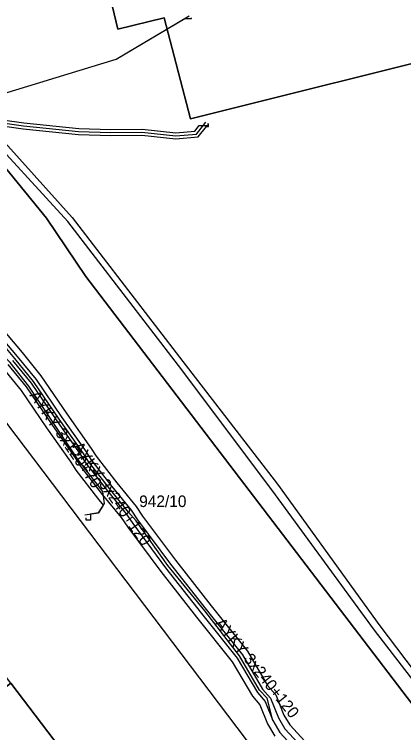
# Model space of a CAD drawing. Extents: x -793400 to -756198, y -1074141 to -1042963.
# Drawn here: x -783067.47 to -783042.2, y -1065160.27 to -1065113.69 of the extents above; entities that cross this region are included whole.
import ezdxf

# ---------------------------------------------------------------- set-up
doc = ezdxf.new("R2010")
doc.units = 0
for name, color, linetype in [('Parcela', 7, 'Continuous'), ('Popiskový text - Parcela', 7, 'Continuous'), ('Popiskový text - Vedení nn kabelové', 7, 'Continuous'), ('Spojnice nn', 7, 'Continuous'), ('Spojnice vn', 7, 'Continuous'), ('Stavební objekt', 7, 'Continuous'), ('Vedení 22 kV kabelové', 7, 'Continuous'), ('Vedení nn kabelové', 7, 'Continuous')]:
    doc.layers.add(name, color=color, linetype=linetype)

msp = doc.modelspace()

# ---------------------------------------------------------------- linework, layer by layer
at = {"layer": 'Parcela'}
msp.add_lwpolyline([(-783145.19, -1065118.78), (-783065.04, -1065096.7), (-783060.76, -1065114.64), (-783057.74, -1065113.92), (-783056.04, -1065120.47), (-783037.14, -1065115.76), (-783036.87, -1065116.85), (-783031.97, -1065115.65), (-783032.24, -1065114.53), (-783028.46, -1065113.59), (-783029.14, -1065110.87), (-783025.94, -1065110.07), (-783026.78, -1065106.68), (-783029.99, -1065107.48), (-783034.78, -1065088.26), (-783031.87, -1065087.44), (-782993.91, -1065091.32), (-782972.88, -1065081.39), (-782969.74, -1065082.74), (-782964.46, -1065085)], dxfattribs=at)
for points in [[(-783034.78, -1065088.26), (-783029.99, -1065107.48), (-783026.78, -1065106.68), (-783025.94, -1065110.07), (-783029.14, -1065110.87), (-783028.46, -1065113.59), (-783032.24, -1065114.53), (-783031.97, -1065115.65), (-783036.87, -1065116.85), (-783037.14, -1065115.76), (-783056.04, -1065120.47), (-783057.74, -1065113.92), (-783060.76, -1065114.64), (-783065.04, -1065096.7), (-783065.15, -1065096.23), (-783059.74, -1065094.99), (-783061.01, -1065091.04), (-783054.08, -1065089.37), (-783054.18, -1065088.96), (-783035.72, -1065084.5)], [(-783062.82, -1065130.68), (-783065.38, -1065126.9), (-783070.16, -1065121.07), (-783078.17, -1065126.78), (-783086.05, -1065132.94), (-783082.37, -1065137.77), (-783083.31, -1065138.48), (-783079.56, -1065143.43), (-783078.61, -1065142.71), (-783071.47, -1065152.1), (-783072.41, -1065152.82), (-783068.64, -1065157.77), (-783067.7, -1065157.05), (-783060.55, -1065166.44), (-783061.49, -1065167.16), (-783057.74, -1065172.09), (-783056.8, -1065171.37), (-783053.14, -1065176.18), (-783045.29, -1065170.16), (-783037.3, -1065164.1)], [(-783062.82, -1065130.68), (-783037.3, -1065164.1), (-783045.29, -1065170.16), (-783053.14, -1065176.18), (-783056.8, -1065171.37), (-783057.74, -1065172.09), (-783061.49, -1065167.16), (-783060.55, -1065166.44), (-783067.7, -1065157.05), (-783068.64, -1065157.77), (-783072.41, -1065152.82), (-783071.47, -1065152.1), (-783078.61, -1065142.71), (-783079.56, -1065143.43), (-783083.31, -1065138.48), (-783082.37, -1065137.77), (-783086.05, -1065132.94), (-783078.17, -1065126.78), (-783070.16, -1065121.07), (-783065.38, -1065126.9)]]:
    msp.add_lwpolyline(points, close=True, dxfattribs=at)
at = {"layer": 'Spojnice nn'}
for points in [[(-783078.01, -1065124.77), (-783077.24, -1065124.21), (-783075.95, -1065123.29), (-783072.89, -1065121.04), (-783069.49, -1065120.55), (-783066.87, -1065120.92), (-783063.3, -1065121.29), (-783061.2, -1065121.35), (-783059.19, -1065121.33), (-783056.99, -1065121.57), (-783055.65, -1065121.45), (-783055.03, -1065120.68)], [(-783050.69, -1065159.48), (-783051.06, -1065158.04), (-783051.55, -1065157.52), (-783052.86, -1065155.29), (-783055.11, -1065152.36), (-783057.5, -1065149.43), (-783059.56, -1065146.54), (-783060.05, -1065145.96), (-783061.29, -1065144.44), (-783062.66, -1065142.68), (-783062.98, -1065142.17), (-783064.55, -1065139.94), (-783066.22, -1065137.49), (-783067.43, -1065136.01), (-783068.97, -1065134.2), (-783070.39, -1065132.31), (-783070.82, -1065131.77), (-783072.05, -1065130.11), (-783073.91, -1065127.65), (-783075.94, -1065124.77), (-783078.01, -1065124.77)], [(-783062.9, -1065146.15), (-783062, -1065146.02), (-783061.62, -1065145.4), (-783061.73, -1065144.64), (-783063.32, -1065142.58), (-783064.91, -1065140.21), (-783066.52, -1065137.8), (-783067.74, -1065136.26), (-783069.38, -1065134.66), (-783071.12, -1065132.55), (-783071.99, -1065131.96), (-783072.62, -1065131.68)]]:
    msp.add_lwpolyline(points, dxfattribs=at)
at = {"layer": 'Spojnice vn'}
for points in [[(-783088.517, -1065122.003), (-783087.71, -1065121.756), (-783085.853, -1065126.558), (-783082.374, -1065124.993), (-783081.445, -1065125.449), (-783072.85, -1065119.204), (-783069.736, -1065119.308), (-783060.87, -1065116.592), (-783056.132, -1065113.792)], [(-783090.122, -1065121.728), (-783090.423, -1065122.528), (-783088.58, -1065127.84), (-783087.94, -1065128.77), (-783086.72, -1065129.4), (-783084.2, -1065129.22), (-783079.15, -1065125.34), (-783074.84, -1065122.41), (-783071.77, -1065120.7), (-783069.62, -1065120.31), (-783063.71, -1065126.87), (-783056.53, -1065136.2), (-783050.38, -1065144.16), (-783043.74, -1065153.34), (-783038.74, -1065159.93), (-783035.71, -1065165.52), (-783036.68, -1065170.3), (-783039.01, -1065176.26), (-783037.18, -1065184.02), (-783034.68, -1065192.04), (-783030.73, -1065199.14)], [(-783035.09, -1065192.27), (-783037.33, -1065184.37), (-783039.33, -1065176.44), (-783037.05, -1065170.19), (-783036.06, -1065165.7), (-783039.05, -1065160.14), (-783044.1, -1065153.63), (-783050.75, -1065144.53), (-783056.81, -1065136.46), (-783064, -1065127.13), (-783069.89, -1065120.72), (-783071.65, -1065121.2), (-783074.59, -1065122.82), (-783078.93, -1065125.75), (-783084.07, -1065129.57), (-783086.79, -1065129.72), (-783088.1, -1065129.01), (-783088.87, -1065127.95), (-783090.303, -1065122.562), (-783090.122, -1065121.728)]]:
    msp.add_lwpolyline(points, dxfattribs=at)
at = {"layer": 'Stavební objekt'}
for points in [[(-783028.46, -1065113.59), (-783032.24, -1065114.53), (-783037.14, -1065115.76), (-783056.04, -1065120.47), (-783057.74, -1065113.92), (-783060.76, -1065114.64), (-783065.04, -1065096.7), (-783065.15, -1065096.23), (-783059.74, -1065094.99), (-783061.01, -1065091.04), (-783054.08, -1065089.37), (-783054.18, -1065088.96), (-783035.72, -1065084.5), (-783034.78, -1065088.26), (-783029.99, -1065107.48), (-783029.14, -1065110.87)], [(-783045.29, -1065170.16), (-783053.14, -1065176.18), (-783056.8, -1065171.37), (-783060.55, -1065166.44), (-783067.7, -1065157.05), (-783071.47, -1065152.1), (-783078.61, -1065142.71), (-783082.37, -1065137.77), (-783086.05, -1065132.94), (-783078.17, -1065126.78)]]:
    msp.add_lwpolyline(points, close=True, dxfattribs=at)
at = {"layer": 'Vedení 22 kV kabelové'}
for points in [[(-783089.882, -1065121.838), (-783089.882, -1065122.003), (-783088.517, -1065122.003), (-783087.71, -1065121.756), (-783085.853, -1065126.558), (-783082.374, -1065124.993), (-783081.445, -1065125.449), (-783072.854, -1065119.132), (-783069.736, -1065119.308), (-783060.87, -1065116.592), (-783056.409, -1065113.955), (-783055.971, -1065113.955), (-783055.972, -1065113.921)], [(-783089.792, -1065121.838), (-783089.792, -1065121.984), (-783089.611, -1065121.984), (-783089.611, -1065122.559), (-783090.412, -1065122.559), (-783088.58, -1065127.84), (-783087.94, -1065128.77), (-783086.72, -1065129.4), (-783084.2, -1065129.22), (-783079.15, -1065125.34), (-783074.84, -1065122.41), (-783071.77, -1065120.7), (-783069.62, -1065120.31), (-783063.71, -1065126.87), (-783056.53, -1065136.2), (-783050.38, -1065144.16), (-783043.74, -1065153.34), (-783038.74, -1065159.93), (-783035.71, -1065165.52), (-783036.68, -1065170.3), (-783039.01, -1065176.26), (-783037.18, -1065184.02), (-783034.68, -1065192.04), (-783030.73, -1065199.14)], [(-783035.09, -1065192.27), (-783037.33, -1065184.37), (-783039.33, -1065176.44), (-783037.05, -1065170.19), (-783036.06, -1065165.7), (-783039.05, -1065160.14), (-783044.1, -1065153.63), (-783050.75, -1065144.53), (-783056.81, -1065136.46), (-783064, -1065127.13), (-783069.89, -1065120.72), (-783071.65, -1065121.2), (-783074.59, -1065122.82), (-783078.93, -1065125.75), (-783084.07, -1065129.57), (-783086.79, -1065129.72), (-783088.1, -1065129.01), (-783088.87, -1065127.95), (-783090.303, -1065122.562), (-783090.177, -1065121.982), (-783089.972, -1065121.982), (-783089.972, -1065121.838)]]:
    msp.add_lwpolyline(points, dxfattribs=at)
at = {"layer": 'Vedení nn kabelové'}
for points in [[(-783089.974, -1065122.157), (-783089.974, -1065122.332), (-783088.005, -1065122.332), (-783086.079, -1065126.587), (-783085.279, -1065126.75), (-783083.21, -1065125.501), (-783080.476, -1065123.994), (-783078.181, -1065123.581), (-783076.439, -1065123.393), (-783076.067, -1065123.128), (-783072.968, -1065120.849), (-783069.49, -1065120.348), (-783066.846, -1065120.721), (-783063.287, -1065121.09), (-783061.198, -1065121.15), (-783059.18, -1065121.13), (-783056.988, -1065121.369), (-783055.753, -1065121.258), (-783055.467, -1065120.904), (-783054.897, -1065120.904), (-783054.897, -1065120.769)], [(-783089.999, -1065122.157), (-783089.999, -1065122.392), (-783088.417, -1065122.392), (-783086.36, -1065126.938), (-783085.206, -1065127.174), (-783083.01, -1065125.847), (-783080.341, -1065124.376), (-783078.124, -1065123.978), (-783076.292, -1065123.779), (-783075.833, -1065123.452), (-783072.812, -1065121.231), (-783069.49, -1065120.752), (-783066.894, -1065121.119), (-783063.313, -1065121.49), (-783061.202, -1065121.55), (-783059.2, -1065121.53), (-783056.992, -1065121.771), (-783055.547, -1065121.642), (-783054.992, -1065120.952), (-783054.873, -1065120.952), (-783054.873, -1065120.769)], [(-783073.93, -1065131.88), (-783073.9, -1065132.078), (-783072.281, -1065131.831), (-783071.99, -1065131.96), (-783071.857, -1065132.05), (-783071.613, -1065132.379), (-783071.181, -1065132.922), (-783069.751, -1065134.825), (-783068.198, -1065136.65), (-783067.022, -1065138.089), (-783065.372, -1065140.509), (-783063.813, -1065142.724), (-783063.48, -1065143.254), (-783062.072, -1065145.063), (-783061.696, -1065145.524), (-783062, -1065146.02), (-783062.527, -1065146.096), (-783062.527, -1065146.499), (-783062.813, -1065146.499), (-783062.813, -1065146.328)], [(-783068.501, -1065133.825), (-783066.969, -1065135.626), (-783065.739, -1065137.13), (-783064.057, -1065139.598), (-783062.48, -1065141.838), (-783062.168, -1065142.335), (-783060.821, -1065144.066), (-783059.561, -1065145.611), (-783059.147, -1065146.233), (-783057.013, -1065149.092), (-783054.7, -1065152.039), (-783052.34, -1065154.986), (-783051.031, -1065157.201), (-783050.49, -1065157.821), (-783049.97, -1065159.125), (-783049.586, -1065159.768), (-783046.662, -1065162.934)], [(-783068.814, -1065134.075), (-783067.276, -1065135.882), (-783066.06, -1065137.37), (-783064.386, -1065139.826), (-783062.813, -1065142.059), (-783062.496, -1065142.565), (-783061.134, -1065144.315), (-783059.883, -1065145.849), (-783059.468, -1065146.472), (-783057.331, -1065149.336), (-783055.013, -1065152.287), (-783052.67, -1065155.214), (-783051.357, -1065157.437), (-783050.836, -1065158.032), (-783050.33, -1065159.302), (-783049.908, -1065160.009), (-783046.996, -1065163.162)], [(-783067.584, -1065136.138), (-783066.38, -1065137.61), (-783064.714, -1065140.054), (-783063.147, -1065142.281), (-783062.824, -1065142.795), (-783061.446, -1065144.565), (-783060.205, -1065146.086), (-783059.788, -1065146.711), (-783057.648, -1065149.579), (-783055.327, -1065152.535), (-783053, -1065155.442), (-783051.682, -1065157.672), (-783051.182, -1065158.244), (-783050.69, -1065159.48), (-783050.23, -1065160.25), (-783047.33, -1065163.39)], [(-783067.891, -1065136.394), (-783066.701, -1065137.85), (-783065.043, -1065140.282), (-783063.48, -1065142.502), (-783063.152, -1065143.025), (-783061.759, -1065144.814), (-783060.527, -1065146.324), (-783060.109, -1065146.951), (-783057.966, -1065149.822), (-783055.64, -1065152.784), (-783053.33, -1065155.67), (-783052.008, -1065157.908), (-783051.528, -1065158.456), (-783051.033, -1065159.685), (-783050.552, -1065160.491)]]:
    msp.add_lwpolyline(points, dxfattribs=at)

# ---------------------------------------------------------------- texts
at = {"layer": 'Popiskový text - Parcela'}
msp.add_text('942/10', height=0.75, dxfattribs=at).set_placement((-783059.365, -1065145.638))
at = {"layer": 'Popiskový text - Vedení nn kabelové'}
for s, rotation, p in [('AYKY 3x120+70', 304.2979, (-783066.514, -1065138.39)), ('AYKY 3x240+120', 305.1573, (-783063.72, -1065141.727)), ('AYKY 3x240+120', 308.7097, (-783054.478, -1065153.196))]:
    msp.add_text(s, height=0.75, rotation=rotation, dxfattribs=at).set_placement(p)

doc.saveas('drawing.dxf')
